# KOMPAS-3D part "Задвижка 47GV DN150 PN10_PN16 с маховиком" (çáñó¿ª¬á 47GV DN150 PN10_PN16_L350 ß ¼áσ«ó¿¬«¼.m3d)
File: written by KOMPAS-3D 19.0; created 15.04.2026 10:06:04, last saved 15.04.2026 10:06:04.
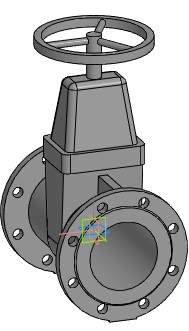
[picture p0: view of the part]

Document properties: Автор: Евгений; Полное имя файла: Z:\3.Личные\kachalov\3d для проектировщиков\2.1 Тип 47GV, 47GV.Z\Задвижка 47GV_DN40-DN600\stp_Задвижка 47GV\Задвижка 47GV DN150 PN10_PN16_L350 с маховиком.m3d

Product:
- Part/product: Задвижка 47GV DN150 PN10_PN16 с маховиком

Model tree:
1. Операция без истории:1  (labels: Задвижка 47GV DN150 PN10_PN16 с маховиком)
